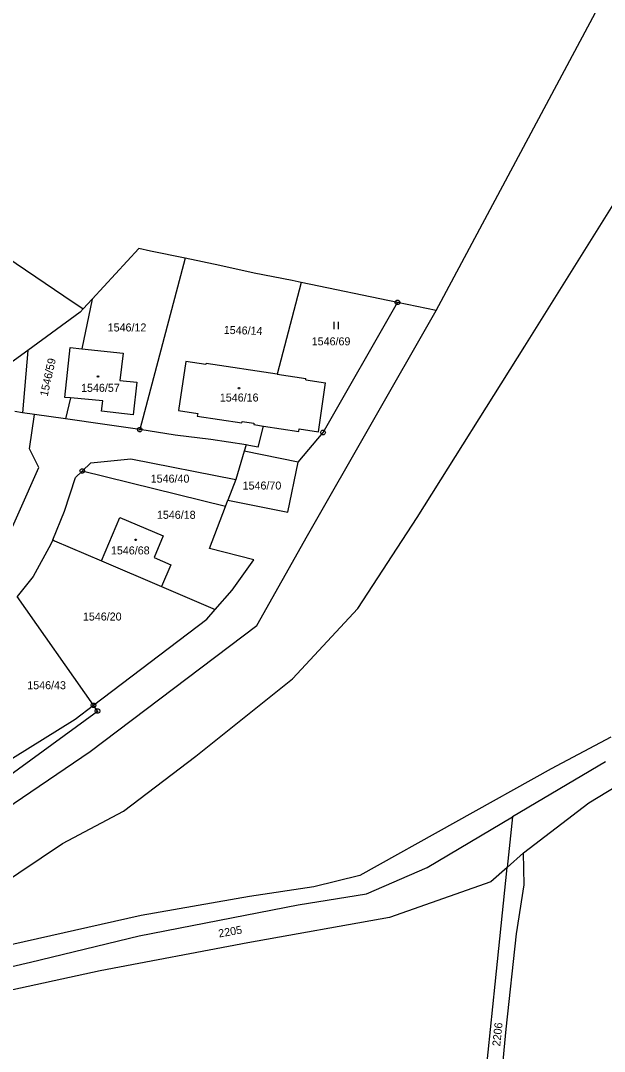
# Model space of a CAD drawing. Extents: x -609861 to -605046, y -1120287 to -1116307.
# Drawn here: x -606650.3 to -606526.3, y -1118973.8 to -1118754.8 of the extents above; entities that cross this region are included whole.
import ezdxf

# ---------------------------------------------------------------- set-up
doc = ezdxf.new("R2010")
doc.units = 0
for name, color, linetype in [('Vrstva 1', 7, 'Continuous'), ('Vrstva 2', 7, 'Continuous'), ('Vrstva 3', 7, 'Continuous'), ('Vrstva 5', 7, 'Continuous'), ('Vrstva 8', 7, 'Continuous')]:
    doc.layers.add(name, color=color, linetype=linetype)

msp = doc.modelspace()

# ---------------------------------------------------------------- linework, layer by layer
at = {"layer": 'Vrstva 1'}
for p, q in [((-606562.07, -1118816.38), (-606526.57, -1118749.95)), ((-606543.19, -1118824), (-606524.1, -1118793.37)), ((-606658.92, -1118801.27), (-606641.12, -1118813.3)), ((-606625.22, -1118803.24), (-606635.14, -1118814.01)), ((-606622.76, -1118803.75), (-606625.22, -1118803.24)), ((-606615.38, -1118805.28), (-606625.01, -1118841.7)), ((-606615.38, -1118805.28), (-606622.76, -1118803.75)), ((-606608.01, -1118806.82), (-606615.38, -1118805.28)), ((-606600.69, -1118808.43), (-606608.01, -1118806.82)), ((-606592.67, -1118810.03), (-606600.69, -1118808.43)), ((-606590.7, -1118810.42), (-606592.67, -1118810.03)), ((-606590.7, -1118810.42), (-606595.81, -1118829.92)), ((-606570.26, -1118814.68), (-606590.7, -1118810.42)), ((-606641.12, -1118813.3), (-606637.03, -1118816.06)), ((-606635.14, -1118814.01), (-606637.34, -1118824.5)), ((-606635.14, -1118814.01), (-606637.03, -1118816.06)), ((-606637.65, -1118816.73), (-606648.8, -1118824.86)), ((-606637.03, -1118816.06), (-606637.65, -1118816.73)), ((-606589.42, -1118864.18), (-606562.07, -1118816.38)), ((-606586.08, -1118842.32), (-606570.26, -1118814.68)), ((-606562.07, -1118816.38), (-606570.26, -1118814.68)), ((-606648.8, -1118824.86), (-606657.35, -1118831.09)), ((-606648.8, -1118824.86), (-606649.9, -1118838.12)), ((-606640.93, -1118834.84), (-606639.78, -1118824.24)), ((-606639.78, -1118824.24), (-606637.34, -1118824.5)), ((-606637.34, -1118824.5), (-606628.54, -1118825.45)), ((-606628.54, -1118825.45), (-606629.21, -1118831.24)), ((-606566.07, -1118860.39), (-606543.19, -1118824)), ((-606615.22, -1118827.22), (-606616.81, -1118837.63)), ((-606610.98, -1118827.88), (-606615.22, -1118827.22)), ((-606610.93, -1118827.63), (-606610.98, -1118827.88)), ((-606595.81, -1118829.92), (-606610.93, -1118827.63)), ((-606629.21, -1118831.24), (-606625.64, -1118831.65)), ((-606625.64, -1118831.65), (-606626.43, -1118838.54)), ((-606595.81, -1118829.92), (-606589.71, -1118830.84)), ((-606589.74, -1118831.12), (-606589.71, -1118830.84)), ((-606589.74, -1118831.12), (-606585.55, -1118831.77)), ((-606587.06, -1118842.18), (-606585.55, -1118831.77)), ((-606639.75, -1118834.95), (-606640.93, -1118834.84)), ((-606639.75, -1118834.95), (-606640.78, -1118839.43)), ((-606632.87, -1118835.6), (-606639.75, -1118834.95)), ((-606633.12, -1118837.79), (-606632.87, -1118835.6)), ((-606649.9, -1118838.12), (-606651.58, -1118837.86)), ((-606647.38, -1118838.49), (-606649.9, -1118838.12)), ((-606648.41, -1118845.78), (-606647.38, -1118838.49)), ((-606640.78, -1118839.43), (-606647.38, -1118838.49)), ((-606626.43, -1118838.54), (-606633.12, -1118837.79)), ((-606616.81, -1118837.63), (-606612.71, -1118838.26)), ((-606612.71, -1118838.26), (-606612.81, -1118838.81)), ((-606632.46, -1118840.6), (-606640.78, -1118839.43)), ((-606625.01, -1118841.7), (-606632.46, -1118840.6)), ((-606612.81, -1118838.81), (-606603.33, -1118840.23)), ((-606603.33, -1118840.23), (-606603.29, -1118839.95)), ((-606603.29, -1118839.95), (-606600.76, -1118840.33)), ((-606600.76, -1118840.33), (-606600.79, -1118840.63)), ((-606600.79, -1118840.63), (-606598.7, -1118840.95)), ((-606599.87, -1118845.41), (-606598.7, -1118840.95)), ((-606598.7, -1118840.95), (-606591.23, -1118842.08)), ((-606591.36, -1118848.62), (-606586.08, -1118842.32)), ((-606591.23, -1118842.08), (-606591.15, -1118841.55)), ((-606591.15, -1118841.55), (-606587.06, -1118842.18)), ((-606602.44, -1118844.94), (-606602.83, -1118846.26)), ((-606601.85, -1118845.1), (-606602.44, -1118844.94)), ((-606599.87, -1118845.41), (-606601.85, -1118845.1)), ((-606646.48, -1118849.73), (-606648.41, -1118845.78)), ((-606602.83, -1118846.26), (-606604.61, -1118852.28)), ((-606591.36, -1118848.62), (-606602.83, -1118846.26)), ((-606637.22, -1118850.49), (-606635.39, -1118848.72)), ((-606635.39, -1118848.72), (-606626.94, -1118847.91)), ((-606626.94, -1118847.91), (-606604.61, -1118852.28)), ((-606593.59, -1118859.25), (-606591.36, -1118848.62)), ((-606655.14, -1118869.24), (-606646.48, -1118849.73)), ((-606606.81, -1118858.04), (-606637.22, -1118850.49)), ((-606604.61, -1118852.28), (-606606.3, -1118856.7)), ((-606610.19, -1118866.92), (-606606.81, -1118858.04)), ((-606606.81, -1118858.04), (-606606.3, -1118856.7)), ((-606606.3, -1118856.7), (-606593.59, -1118859.25)), ((-606578.72, -1118879.71), (-606566.07, -1118860.39)), ((-606600.13, -1118883.29), (-606589.42, -1118864.18)), ((-606643.88, -1118866.06), (-606647.64, -1118872.9)), ((-606643.5, -1118865.14), (-606643.88, -1118866.06)), ((-606643.5, -1118865.14), (-606643.11, -1118865.31)), ((-606643.11, -1118865.31), (-606633.17, -1118869.55)), ((-606600.76, -1118869.34), (-606610.19, -1118866.92)), ((-606633.17, -1118869.55), (-606620.36, -1118875.02)), ((-606605.42, -1118875.81), (-606600.76, -1118869.34)), ((-606647.64, -1118872.9), (-606651.07, -1118877.13)), ((-606620.36, -1118875.02), (-606608.98, -1118879.89)), ((-606608.98, -1118879.89), (-606605.42, -1118875.81)), ((-606634.83, -1118900.26), (-606651.07, -1118877.13)), ((-606610.79, -1118881.96), (-606608.98, -1118879.89)), ((-606592.59, -1118894.67), (-606578.72, -1118879.71)), ((-606634.83, -1118900.26), (-606610.79, -1118881.96)), ((-606635.58, -1118910.11), (-606600.13, -1118883.29)), ((-606613.13, -1118911.1), (-606592.59, -1118894.67)), ((-606662.18, -1118922.04), (-606633.97, -1118901.49)), ((-606638.73, -1118903.23), (-606634.83, -1118900.26)), ((-606633.97, -1118901.49), (-606634.83, -1118900.26)), ((-606662.47, -1118917.95), (-606638.73, -1118903.23)), ((-606529.65, -1118921.02), (-606501.9, -1118903.96)), ((-606524.96, -1118907.02), (-606537.63, -1118913.75)), ((-606656.58, -1118924.36), (-606635.58, -1118910.11)), ((-606628.46, -1118922.78), (-606613.13, -1118911.1)), ((-606526.09, -1118912.31), (-606545.85, -1118923.99)), ((-606537.63, -1118913.75), (-606578.25, -1118936.46)), ((-606543.48, -1118931.64), (-606529.65, -1118921.02)), ((-606641.45, -1118929.66), (-606628.46, -1118922.78)), ((-606563.98, -1118934.7), (-606545.85, -1118923.99)), ((-606545.85, -1118923.99), (-606546.96, -1118934.71)), ((-606659.33, -1118941.6), (-606641.45, -1118929.66)), ((-606543.48, -1118931.64), (-606546.96, -1118934.71)), ((-606543.35, -1118938.42), (-606543.48, -1118931.64)), ((-606576.88, -1118940.29), (-606563.98, -1118934.7)), ((-606546.96, -1118934.71), (-606550.45, -1118937.78)), ((-606549.53, -1118959.48), (-606546.96, -1118934.71)), ((-606578.25, -1118936.46), (-606588.01, -1118938.82)), ((-606588.01, -1118938.82), (-606601.7, -1118940.9)), ((-606550.45, -1118937.78), (-606571.97, -1118945.37)), ((-606544.98, -1118948.83), (-606543.35, -1118938.42)), ((-606601.7, -1118940.9), (-606624.72, -1118944.9)), ((-606591.4, -1118942.64), (-606576.88, -1118940.29)), ((-606625.14, -1118949.27), (-606591.4, -1118942.64)), ((-606624.72, -1118944.9), (-606661.48, -1118953.19)), ((-606571.97, -1118945.37), (-606602.04, -1118950.7)), ((-606648.19, -1118954.83), (-606625.14, -1118949.27)), ((-606547.22, -1118969.06), (-606544.98, -1118948.83)), ((-606602.04, -1118950.7), (-606633.43, -1118956.67)), ((-606678.19, -1118961.89), (-606648.19, -1118954.83)), ((-606633.43, -1118956.67), (-606667.62, -1118964.14)), ((-606553.13, -1118993.92), (-606549.53, -1118959.48)), ((-606550.06, -1118999.63), (-606547.22, -1118969.06))]:
    msp.add_line(p, q, dxfattribs=at)
for points in [[(-606602.44, -1118844.94), (-606609.91, -1118843.81), (-606617.51, -1118842.88), (-606625.01, -1118841.7)], [(-606643.5, -1118865.14), (-606640.98, -1118858.99), (-606638.66, -1118851.88), (-606637.22, -1118850.49)], [(-606633.17, -1118869.55), (-606629.24, -1118860.36), (-606620.02, -1118864.29), (-606621.98, -1118868.88), (-606618.4, -1118870.4), (-606620.36, -1118875.02)]]:
    msp.add_lwpolyline(points, dxfattribs=at)
at = {"layer": 'Vrstva 3'}
for p, q in [((-606583.8, -1118818.83), (-606583.8, -1118820.33)), ((-606582.8, -1118820.33), (-606582.8, -1118818.83))]:
    msp.add_line(p, q, dxfattribs=at)
at = {"layer": 'Vrstva 5'}
for points in [[(-606633.8, -1118830.27), (-606633.71, -1118830.42), (-606633.8, -1118830.57), (-606633.98, -1118830.57), (-606634.07, -1118830.42), (-606633.98, -1118830.27)], [(-606603.84, -1118832.72), (-606603.75, -1118832.87), (-606603.84, -1118833.02), (-606604.02, -1118833.02), (-606604.11, -1118832.87), (-606604.02, -1118832.72)], [(-606625.8, -1118864.96), (-606625.71, -1118865.11), (-606625.8, -1118865.26), (-606625.98, -1118865.26), (-606626.07, -1118865.11), (-606625.98, -1118864.96)]]:
    msp.add_lwpolyline(points, close=True, dxfattribs=at)
at = {"layer": 'Vrstva 8'}
for p, q in [((-606570.38, -1118814.68), (-606570.14, -1118814.68)), ((-606625.13, -1118841.7), (-606624.89, -1118841.7)), ((-606586.2, -1118842.32), (-606585.96, -1118842.32)), ((-606637.34, -1118850.49), (-606637.1, -1118850.49)), ((-606634.95, -1118900.26), (-606634.71, -1118900.26)), ((-606634.09, -1118901.49), (-606633.85, -1118901.49))]:
    msp.add_line(p, q, dxfattribs=at)
for points in [[(-606570.11, -1118814.2), (-606569.86, -1118814.38), (-606569.76, -1118814.67), (-606569.86, -1118814.96), (-606570.11, -1118815.14), (-606570.42, -1118815.14), (-606570.67, -1118814.96), (-606570.77, -1118814.67), (-606570.67, -1118814.38), (-606570.42, -1118814.2)], [(-606624.86, -1118841.22), (-606624.61, -1118841.4), (-606624.51, -1118841.69), (-606624.61, -1118841.98), (-606624.86, -1118842.16), (-606625.17, -1118842.16), (-606625.42, -1118841.98), (-606625.52, -1118841.69), (-606625.42, -1118841.4), (-606625.17, -1118841.22)], [(-606585.93, -1118841.84), (-606585.68, -1118842.02), (-606585.58, -1118842.31), (-606585.68, -1118842.6), (-606585.93, -1118842.78), (-606586.24, -1118842.78), (-606586.49, -1118842.6), (-606586.59, -1118842.31), (-606586.49, -1118842.02), (-606586.24, -1118841.84)], [(-606637.07, -1118850.01), (-606636.82, -1118850.19), (-606636.72, -1118850.48), (-606636.82, -1118850.77), (-606637.07, -1118850.95), (-606637.38, -1118850.95), (-606637.63, -1118850.77), (-606637.73, -1118850.48), (-606637.63, -1118850.19), (-606637.38, -1118850.01)], [(-606634.68, -1118899.78), (-606634.43, -1118899.96), (-606634.33, -1118900.25), (-606634.43, -1118900.54), (-606634.68, -1118900.72), (-606634.99, -1118900.72), (-606635.24, -1118900.54), (-606635.34, -1118900.25), (-606635.24, -1118899.96), (-606634.99, -1118899.78)], [(-606633.82, -1118901.01), (-606633.57, -1118901.19), (-606633.47, -1118901.48), (-606633.57, -1118901.77), (-606633.82, -1118901.95), (-606634.13, -1118901.95), (-606634.38, -1118901.77), (-606634.48, -1118901.48), (-606634.38, -1118901.19), (-606634.13, -1118901.01)]]:
    msp.add_lwpolyline(points, close=True, dxfattribs=at)

# ---------------------------------------------------------------- texts
at = {"layer": 'Vrstva 2'}
for s, p in [('1546/12', (-606631.827, -1118820.84)), ('1546/69', (-606588.491, -1118823.79)), ('1546/57', (-606637.477, -1118833.67)), ('1546/16', (-606608.003, -1118835.73)), ('1546/40', (-606622.687, -1118852.96)), ('1546/70', (-606603.167, -1118854.43)), ('1546/18', (-606621.367, -1118860.65)), ('1546/68', (-606631.131, -1118868.21)), ('1546/20', (-606637.087, -1118882.26)), ('1546/43', (-606648.907, -1118896.85))]:
    msp.add_text(s, height=1.7, dxfattribs=at).set_placement(p)
for s, rotation, p in [('1546/14', 358.21321, (-606607.187, -1118821.342)), ('1546/59', 77.4066, (-606644.594, -1118834.757)), ('2205', 9.96947, (-606608.156, -1118949.609)), ('2206', 83.99561, (-606548.465, -1118972.784))]:
    msp.add_text(s, height=1.7, rotation=rotation, dxfattribs=at).set_placement(p)

doc.saveas('drawing.dxf')
